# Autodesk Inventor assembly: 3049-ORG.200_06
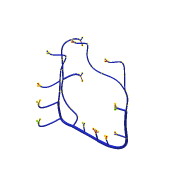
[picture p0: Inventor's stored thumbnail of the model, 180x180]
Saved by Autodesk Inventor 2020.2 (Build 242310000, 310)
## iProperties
Part Number: 3049-ORG.200_06
Material: Ogólne
Description: 3049-ORG
Part Number: 3047-BLU.200_02
Description: 3047-BLU
Part Number: 3047-BLK.200_01
Description: 3047-BLK
Part Number: 3049-GRY.200_04
Description: 3049-GRY
Part Number: 3049-GRN.200_03
Description: 3049-GRN
Part Number: 3049-GRY.200_05
Part Number: 3047-VIO.200_08
Description: 3047-VIO
Part Number: 3251-BRN.400_C12
Description: 3251-BRN
Part Number: 3047-RED.300_L12
Description: 3047-RED
Part Number: 3047-ORG.300_L11
Description: 3047-ORG
Part Number: 3251-BLU.400_C11
Description: 3251-BLU
Part Number: 3251-BLU.400_C22
Part Number: 3251-BRN.400_C21
Part Number: 3047-RED.200_07
ParentFileIdentifier: 5|1|0|0|62|1|0|0|80|0|65|0|84|0|72|0|83|0|59|0|67|0|58|0|92|0|90|0|98|0|105|0|243|0|114|0|32|0|7|1|119|0|105|0|99|0|122|0|101|0|68|1|32|0|65|0|73|0|32|0|50|0|48
Part Number: 3047-VIO.200_10
Part Number: 3047-RED.200_09
Manager: www.cadconsulting.pl
Company: Fabian Stasiak CAD Consulting
Created: 2014-09
Part Number: W_200_01_P2.Wiązka przewodów3
Document SubType Name: Assembly
Designer: F.Stasiak
Catalog Web Link: www.expertbooks.pl
HarnessSettings: <HarnessSettings><Defaults><Segments><Diameter value="0.200 in" fromwires="True"/><Offset value="0.100 in"/><ColorStyle value="Niebieska - farba ścienna - lśnią
Author: F.Stasiak
Subject: Zbiór ćwiczeń. Autodesk Inventor 2020. Kurs Professional
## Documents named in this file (2)
- C:\2020_Kurs_Professional\R2 Wiązki\W_200_01_P2\AIP\przewody i wiązki przewodów\W_200_01_P2.Wiązka przewodów3.iam
- C:\2020_Kurs_Professional\R2 Wiązki\W_200_01_P2\AIP\przewody i wiązki przewodów\W_200_01_P2.Wiązka przewodów3.ipt
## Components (17 placed, 17 different names)
1. Wiązka przewodów3
2. HA_VC_102:1
3. HA_VC_105:1
4. HA_VC_108:1
5. HA_VC_111:1
6. HA_VC_114:1
7. HA_VC_117:1
8. HA_VC_120:1
9. HA_VC_123:1
10. HA_VC_126:1
11. HA_VC_129:1
12. HA_VC_132:1
13. HA_VC_135:1
14. HA_VC_138:1
15. HA_VC_141:1
16. HA_VC_144:1
17. HA_VC_147:1
